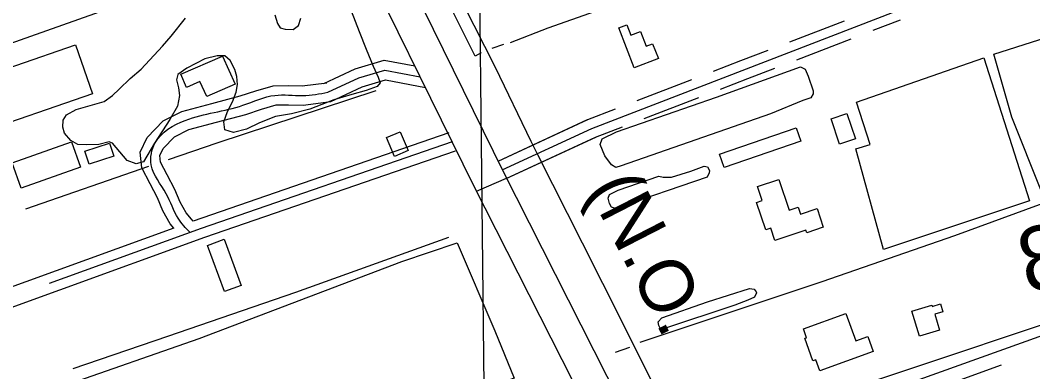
# Model space of a CAD drawing. Extents: x 3684037 to 3722149, y 433263 to 459021.
# Drawn here: x 3703318 to 3704896, y 447025 to 447573 of the extents above; entities that cross this region are included whole.
import ezdxf

# ---------------------------------------------------------------- set-up
doc = ezdxf.new("R2010")
doc.units = 0
for name, color, linetype in [('V-BLDG-OTLN', 7, 'Continuous'), ('V-GRID-MAJR', 7, 'Continuous'), ('V-RAIL-IDEN', 7, 'Continuous'), ('V-RAIL-TRAK', 7, 'Continuous'), ('V-ROAD-CNTR', 7, 'Continuous'), ('V-SITE-VEGE', 7, 'Continuous'), ('V-SURV-IDEN', 7, 'Continuous'), ('V-TOPO-SHOR', 7, 'Continuous')]:
    doc.layers.add(name, color=color, linetype=linetype)

msp = doc.modelspace()

# ---------------------------------------------------------------- linework, layer by layer
at = {"layer": 'V-BLDG-OTLN'}
for points in [[(3704274.546, 447498.401), (3704250.6210000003, 447560.904), (3704263.2430000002, 447565.735), (3704269.481, 447549.43700000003), (3704284.657, 447555.24700000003), (3704293.414, 447532.365), (3704303.433, 447536.199), (3704312.358, 447512.876)], [(3703430.268, 447458.157), (3703243.429, 447393.701), (3703217.049, 447470.16500000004), (3703403.89, 447534.62200000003)], [(3703608.43, 447453.891), (3703597.7970000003, 447477.16500000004), (3703576.84, 447468.055), (3703567.953, 447488.503), (3703633.039, 447516.786), (3703652.824, 447473.091)], [(3704594.87, 447379.844), (3704581.58, 447419.075), (3704606.273, 447427.44), (3704619.562, 447388.21)], [(3704534.3680000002, 447384.509), (3704414.68, 447343.31), (3704407.576, 447363.949), (3704527.261, 447405.14900000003)], [(3703909.863, 447398.931), (3703922.491, 447369.672), (3703900.929, 447360.365), (3703888.779, 447390.08400000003)], [(3703411.632, 447343.803), (3703319.207, 447311.24), (3703305.324, 447350.654), (3703397.7460000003, 447383.215)], [(3703463.4930000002, 447361.08), (3703424.929, 447348.454), (3703418.259, 447368.832), (3703456.827, 447381.45)], [(3704500.113, 447324.681), (3704516.061, 447276.80700000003), (3704530.417, 447281.591), (3704533.9990000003, 447270.847), (3704559.636, 447279.39), (3704569.2800000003, 447250.439), (3704543.647, 447241.89900000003), (3704542.3200000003, 447245.886), (3704494.0470000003, 447229.805), (3704487.602, 447249.157), (3704479.647, 447246.505), (3704465.502, 447288.972), (3704474.052, 447291.821), (3704466.8140000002, 447313.58900000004)], [(3703635.582, 447231.737), (3703662.165, 447159.92600000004), (3703636.113, 447150.282), (3703609.532, 447222.093)], [(3704647.004, 447056.706), (3704563.8850000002, 447026.802), (3704557.77, 447043.802), (3704553.2260000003, 447042.166), (3704540.532, 447077.447), (3704543.358, 447078.46400000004), (3704538.38, 447092.297), (3704604.614, 447116.12700000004), (3704619.98, 447073.416), (3704638.582, 447080.109)], [(3704719.48, 447080.62700000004), (3704707.52, 447119.859), (3704738.523, 447129.31), (3704739.198, 447127.096), (3704752.16, 447131.049), (3704755.879, 447118.853), (3704743.092, 447114.954), (3704750.659, 447090.134)]]:
    msp.add_lwpolyline(points, close=True, dxfattribs=at)
at = {"layer": 'V-GRID-MAJR'}
msp.add_spline([(3704135.699, 438862.184), (3704065.218, 444919.145), (3703994.696, 450979.575), (3703924.1750000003, 457040.012), (3703924.1350000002, 457043.472)], degree=3, dxfattribs=at)
at = {"layer": 'V-RAIL-TRAK'}
msp.add_lwpolyline([(3704660.1410000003, 446294.66000000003), (3704612.173, 446391.696), (3704555.771, 446508.246), (3704497.788, 446618.465), (3704417.666, 446779.83900000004), (3704373.997, 446867.979), (3704352.5130000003, 446909.369), (3704257.423, 447099.952), (3704194.168, 447225.468), (3704124.497, 447363.04000000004), (3704114.046, 447383.678), (3704058.699, 447499.17100000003), (3703975.9420000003, 447662.128)], dxfattribs=at)
at = {"layer": 'V-ROAD-CNTR'}
for points in [[(3703253.202454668, 448978.324017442), (3703572.7738155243, 448329.01131606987), (3703735.227490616, 448010.728952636), (3703782.15039677, 447919.6751347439), (3703807.5763459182, 447877.299219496), (3703867.629225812, 447749.22747563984), (3704070.176820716, 447337.39329931), (3704292.9863750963, 446898.8891763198), (3704318.54932397, 446848.001278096), (3704583.6117938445, 446323.54432701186), (3704886.4781881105, 445717.9925381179), (3705131.8036974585, 445231.3645113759), (3705345.6882696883, 444802.6553687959)], [(3703205.810549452, 448953.1410678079), (3703527.118906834, 448306.12636184), (3703689.7875814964, 447987.4239992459), (3703737.511486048, 447894.815184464), (3703762.44543618, 447853.259267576), (3703821.5943178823, 447727.116519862), (3704024.497912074, 447314.5563449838), (3704247.405466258, 446875.86022237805), (3704272.943415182, 446825.02232405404), (3704537.9858850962, 446300.6043728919), (3704840.840279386, 445695.0765839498), (3705086.1547887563, 445208.47055716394), (3705299.991361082, 444779.857414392)], [(3704069.025823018, 447339.7342946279), (3704208.363544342, 447404.327165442), (3704684.091592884, 447587.3537993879), (3704980.17800071, 447698.38657732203), (3705119.618721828, 447710.96055217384)], [(3704517.297926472, 447539.2558955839), (3704602.249756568, 447571.93883021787)], [(3704647.001667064, 447557.0118600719), (3704689.4775821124, 447573.3538273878)], [(3704528.069904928, 447511.25595158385), (3704613.021735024, 447543.93888621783)], [(3703791.01537904, 447474.16302577), (3703839.8722813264, 447496.9709801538), (3703885.1661907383, 447510.528953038), (3703932.549095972, 447501.51497106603)], [(3704440.842079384, 447509.8399544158), (3704483.316994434, 447526.181921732)], [(3703797.36036635, 447460.57105295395), (3703845.2242706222, 447482.915008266), (3703885.9601891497, 447495.10898387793), (3703940.834079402, 447484.6690047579)], [(3704398.3661643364, 447493.498987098), (3704440.842079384, 447509.8399544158)], [(3704451.6140578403, 447481.8400104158), (3704494.08897289, 447498.18197773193)], [(3703801.59535788, 447445.994082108), (3703850.5762599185, 447468.8590363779), (3703886.754187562, 447479.6890147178), (3703949.119062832, 447467.82303845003)], [(3704279.433402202, 447447.74207861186), (3704364.385232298, 447480.42501324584)], [(3704409.138142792, 447465.499043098), (3704451.6140578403, 447481.8400104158)], [(3703557.189846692, 447248.921476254), (3703551.547857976, 447255.7494625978), (3703540.072880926, 447276.19142171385), (3703531.633897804, 447296.22038165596), (3703520.1859207, 447318.14533780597), (3703507.1979466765, 447343.1282878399), (3703504.724951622, 447367.13423982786), (3703515.448930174, 447390.34519340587), (3703540.317880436, 447415.8951423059), (3703569.52582202, 447430.7431126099), (3703616.127728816, 447443.1440878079), (3703660.614639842, 447454.7640645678), (3703684.9915910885, 447462.7260486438), (3703712.0665369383, 447470.72303265), (3703736.154488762, 447471.1390318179), (3703757.1154468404, 447470.489033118), (3703795.4353702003, 447475.44702320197)], [(3704290.205380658, 447419.7421346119), (3704375.1572107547, 447452.4250692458)], [(3703587.0637869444, 447259.8644543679), (3703584.7057916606, 447262.7184486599), (3703576.3898082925, 447272.78342853), (3703567.0608269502, 447289.39939529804), (3703558.799843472, 447309.0083560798), (3703546.791867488, 447332.007310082), (3703536.453888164, 447351.89227031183), (3703535.4108902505, 447362.02225005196), (3703540.5288800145, 447373.10122789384), (3703558.3458443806, 447391.4051912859), (3703580.2998004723, 447402.56516896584), (3703623.77571352, 447414.136145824), (3703669.0706229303, 447425.96612216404), (3703693.8995732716, 447434.07610594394), (3703716.658527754, 447440.7970925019), (3703735.948489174, 447441.1310918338), (3703758.5854439, 447440.4290932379), (3703801.59535788, 447445.994082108)], [(3704062.716835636, 447353.34326740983), (3704202.5095560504, 447418.1471378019), (3704245.4534701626, 447434.669104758)], [(3704062.716835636, 447353.34326740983), (3704202.0545569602, 447417.9361382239)], [(3704075.3348104, 447326.125321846), (3704214.217532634, 447390.50719308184), (3704256.225448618, 447406.669160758)], [(3703985.8089894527, 447397.45317918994), (3703587.0637869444, 447259.8644543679)], [(3704075.3348104, 447326.125321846), (3704214.672531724, 447390.71819265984)], [(3703995.5949698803, 447369.09323590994), (3703604.8707513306, 447234.27350554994), (3702926.21531372, 446988.66650749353)], [(3703990.701979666, 447383.2732075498), (3703599.8717613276, 447248.41647726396), (3703362.7962354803, 447162.61864885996)], [(3704028.63990379, 447306.40436128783), (3704075.690809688, 447326.54032101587)], [(3704302.0100000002, 446890.327), (3704352.5130000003, 446909.369), (3704388.415, 446921.993), (3704545.316, 446977.142), (3704736.792, 447040.927), (3704901.6720000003, 447096.07300000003), (3705109.768, 447167.167), (3705246.7260000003, 447215.007), (3705452.16, 447284.106), (3705550.559, 447319.322)], [(3703557.189846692, 447248.921476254), (3702917.2629904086, 447017.3341541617)], [(3704325.3000000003, 446841.648), (3704355.884, 446858.26300000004), (3704367.187, 446864.244), (3704373.997, 446867.979), (3704385.963, 446872.63), (3704431.839, 446891.23600000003), (3704547.522, 446931.766), (3704754.286, 447002.197), (3704847.25048615, 447036.4262408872)]]:
    msp.add_lwpolyline(points, dxfattribs=at)
msp.add_spline([(3703582.314796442, 447242.06248997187), (3703563.968833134, 447264.2664455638), (3703545.216870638, 447302.6143688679), (3703521.8259174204, 447347.5102790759), (3703527.988905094, 447381.72321065), (3703574.912811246, 447416.65414078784), (3703664.8426313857, 447440.3650933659), (3703714.362532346, 447455.7600625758), (3703757.85044537, 447455.4590631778), (3703797.36036635, 447460.57105295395)], degree=3, dxfattribs=at)
at = {"layer": 'V-SITE-VEGE'}
for points in [[(3705093.128, 447602.007), (3705162.244, 447389.869), (3704909.541, 447306.13), (3704863.014, 447421.842), (3704835.1040000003, 447519.60000000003)], [(3704819.81, 447514.283), (3704890.918, 447291.504), (3704663.484, 447215.742), (3704620.292, 447372.68200000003), (3704642.236, 447379.32800000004), (3704620.969, 447445.163)], [(3704486.9220000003, 447427.04000000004), (3704254.261, 447345.898), (3704245.968, 447343.281), (3704239.421, 447347.647), (3704228.947, 447361.617), (3704221.532, 447379.076), (3704224.5870000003, 447387.80700000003), (3704246.8510000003, 447399.15), (3704403.122, 447452.808), (3704533.639, 447499.922), (3704541.058, 447496.43), (3704545.859, 447485.517), (3704553.711, 447462.821), (3704553.711, 447458.016), (3704550.215, 447451.907), (3704537.556, 447447.545)], [(3704388.257, 447328.41500000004), (3704245.52, 447279.555), (3704239.409, 447281.739), (3704236.355, 447287.414), (3704234.174, 447295.704), (3704235.921, 447301.381), (3704249.8880000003, 447307.924), (3704313.184, 447329.738), (3704319.7290000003, 447328.427), (3704332.824, 447328.425), (3704362.944, 447337.586), (3704383.897, 447345.438), (3704389.134, 447344.563), (3704392.187, 447338.88800000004), (3704391.751, 447334.96)], [(3703350.2120000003, 446753.678), (3703266.6350000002, 446962.58900000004), (3703384.93, 447003.407), (3703596.4020000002, 447077.178), (3703912.284, 447196.81200000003), (3703998.736, 447226.054), (3704057.225, 447089.061), (3704087.799, 447015.24100000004), (3703834.431, 446923.525), (3703493.279, 446802.566)], [(3704431.431, 447128.933), (3704320.559, 447092.29000000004), (3704315.3200000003, 447093.16500000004), (3704313.139, 447097.529), (3704311.832, 447103.202), (3704317.941, 447109.313), (3704389.095, 447134.178), (3704454.133, 447155.119), (3704461.5530000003, 447154.242), (3704464.609, 447149.878), (3704465.045, 447148.131), (3704461.987, 447141.586), (3704451.512, 447136.78500000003)]]:
    msp.add_lwpolyline(points, close=True, dxfattribs=at)
for points in [[(3703833.6750000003, 447587.466), (3703845.892, 447555.163), (3703856.799, 447527.66500000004), (3703867.705, 447501.036), (3703875.561, 447484.011), (3703878.612, 447475.283), (3703873.81, 447469.61), (3703856.787, 447463.064), (3703834.525, 447456.957), (3703806.588, 447448.67100000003), (3703769.048, 447434.27400000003), (3703740.239, 447426.86), (3703715.794, 447422.936), (3703690.4790000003, 447412.89900000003), (3703670.398, 447403.302), (3703649.882, 447398.069), (3703636.352, 447401.999), (3703635.046, 447414.658), (3703640.721, 447430.37), (3703648.5810000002, 447445.64400000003), (3703654.258, 447460.92), (3703656.443, 447472.704), (3703655.137, 447484.927), (3703652.083, 447495.841), (3703644.852, 447510.254), (3703636.61, 447517.048), (3703624.591, 447517.232), (3703605.383, 447512.436), (3703577.446, 447498.036), (3703563.4760000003, 447488.43700000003), (3703561.291, 447480.147), (3703564.345, 447467.484), (3703565.651, 447455.264), (3703563.0300000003, 447438.679), (3703550.805, 447418.164), (3703526.791, 447381.069), (3703509.764, 447352.266), (3703498.413, 447349.21), (3703484.448, 447354.45300000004), (3703461.699, 447381.36), (3703456.114, 447383.223), (3703440.367, 447379.34), (3703421.599, 447378.906), (3703407.632, 447379.346), (3703396.282, 447385.46), (3703386.685, 447396.81), (3703384.0670000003, 447405.976), (3703384.506, 447417.324), (3703389.745, 447425.181), (3703404.586, 447433.907), (3703426.848, 447440.012), (3703448.237, 447446.121), (3703461.332, 447455.282), (3703471.812, 447465.319), (3703488.8370000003, 447481.902), (3703506.298, 447496.74), (3703539.478, 447532.088), (3703553.011, 447547.8), (3703575.279, 447575.729)], [(3703714.5160000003, 447580.941), (3703718.4420000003, 447567.41000000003), (3703722.805, 447560.863), (3703730.663, 447558.677), (3703742.883, 447558.239), (3703751.614, 447564.348), (3703755.108, 447576.13300000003)]]:
    msp.add_lwpolyline(points, dxfattribs=at)
at = {"layer": 'V-TOPO-SHOR'}
for p, q in [((3704070.856, 447534.835), (3704052.717, 447528.68200000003)), ((3703517.562, 447345.014), (3703326.105, 447278.78500000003)), ((3704267.5670000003, 447063.184), (3704244.957, 447055.20900000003))]:
    msp.add_line(p, q, dxfattribs=at)
for points in [[(3703746.68, 447695.193), (3703549.521, 447624.406), (3703242.309, 447515.418), (3702998.935, 447431.685), (3702891.876, 447391.808)], [(3704398.002, 447651.612), (3704139.954, 447560.461), (3704081.309, 447537.474)], [(3704036.108, 447522.053), (3704026.951, 447516.657), (3703971.8030000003, 447627.431)], [(3705487.542, 447491.46), (3705242.171, 447403.07), (3704979.509, 447312.027), (3704774.035, 447236.93), (3704567.23, 447165.158), (3704283.5270000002, 447071.159)], [(3703871.975, 447462.77), (3703623.944, 447381.032), (3703548.4220000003, 447355.438)], [(3705558.6520000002, 447305.934), (3705295.992, 447216.217), (3704974.815, 447104.572), (3704683.56, 447000.237), (3704473.431, 446929.128), (3704368.613, 446896.043)], [(3703985.436, 447234.42), (3703746.713, 447148.69), (3703547.2260000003, 447080.242), (3703399.419, 447030.093)]]:
    msp.add_lwpolyline(points, dxfattribs=at)

# ---------------------------------------------------------------- texts
at = {"layer": 'V-RAIL-IDEN'}
msp.add_text('(N.O.', height=82.99983200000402, rotation=297.12137225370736, dxfattribs=at).set_placement((3704201.0046524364, 447310.36162435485))
at = {"layer": 'V-SURV-IDEN'}
msp.add_text('859+56.3', height=100, rotation=13.637879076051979, dxfattribs=at).set_placement((3704887.3383816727, 447145.908286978))

doc.saveas('drawing.dxf')
